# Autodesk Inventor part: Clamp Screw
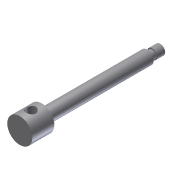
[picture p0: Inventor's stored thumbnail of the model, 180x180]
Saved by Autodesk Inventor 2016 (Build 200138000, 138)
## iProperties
Shininess: 77.0
Length Units: 11269
Angle Units: 11279
Time Units: 11290
Mass Units: 11283
Length Display Precision: 3
Angle Display Precision: 2
Created: 2002-02
Part Number: Clamp Screw
Document SubType Name: Modeling
Designer: ***
Density: 1 g/cm^3
Material: Generic
Mass: 23.4442 g
Surface Area: 81.4176 cm^2
Volume: 23.4442 cm^3
Appearance: Default
Density: 0.0
Volumn: 0.0
Area: 0.0
PropertySet Name: Model Information
Control State: 0
Master: False
Checked Out: False
Author: ***
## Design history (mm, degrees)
sketch "Sketch1"
  geometry: L1 (0, 140)-(5, 140); L2 (5, 140)-(5, 132); L3 (5, 132)-(4, 132); L4 (4, 132)-(4, 127); L5 (4, 127)-(6.5, 127); L6 (6.5, 127)-(6.5, 25); L7 (6.5, 25)-(4, 25); L8 (4, 25)-(4, 22); L9 (4, 22)-(12.5, 22); L10 (12.5, 22)-(12.5, 0); L11 (12.5, 0)-(0, 0); L12 (0, 0)-(0, 140)
  constraints: 24 end point, 10 parallel, 1 horizontal, 1 perpendicular
  dimensions: "d0" = 10 diameter of L2 L12; "d1" = 8 diameter of L4 L12; "d2" = 13 diameter of L6 L12; "d3" = 8 diameter of L7.end L12; "d4" = 25 diameter of L10 L12; "d5" = 3 distance from line of L7.end L9; "d6" = 8 distance of L1.end L2.end; "d7" = 13 vertical distance of L1.end L5.end; "d8" = 22 distance of L9.end L10.end; "d10" = 102 distance of L5.end L6.end
revolve "Revolution1" sketch "Sketch1" stored, may be unused: angle "d11" = 90 deg
sketch "Sketch3"
  geometry: L1 (-12.5, 0)-(12.5, 0) reference; C1 r 5 at (-0.113, 11)
  constraints: 1 centre point
  dimensions: "d13" = 10 diameter of C1; "d14" = 11 distance from line of L1 C1.centre
extrude "Extrusion1" cut sketch "Sketch3" stored distance "d15" = 10; taper "d16" = 0 deg
body "Solid1"
